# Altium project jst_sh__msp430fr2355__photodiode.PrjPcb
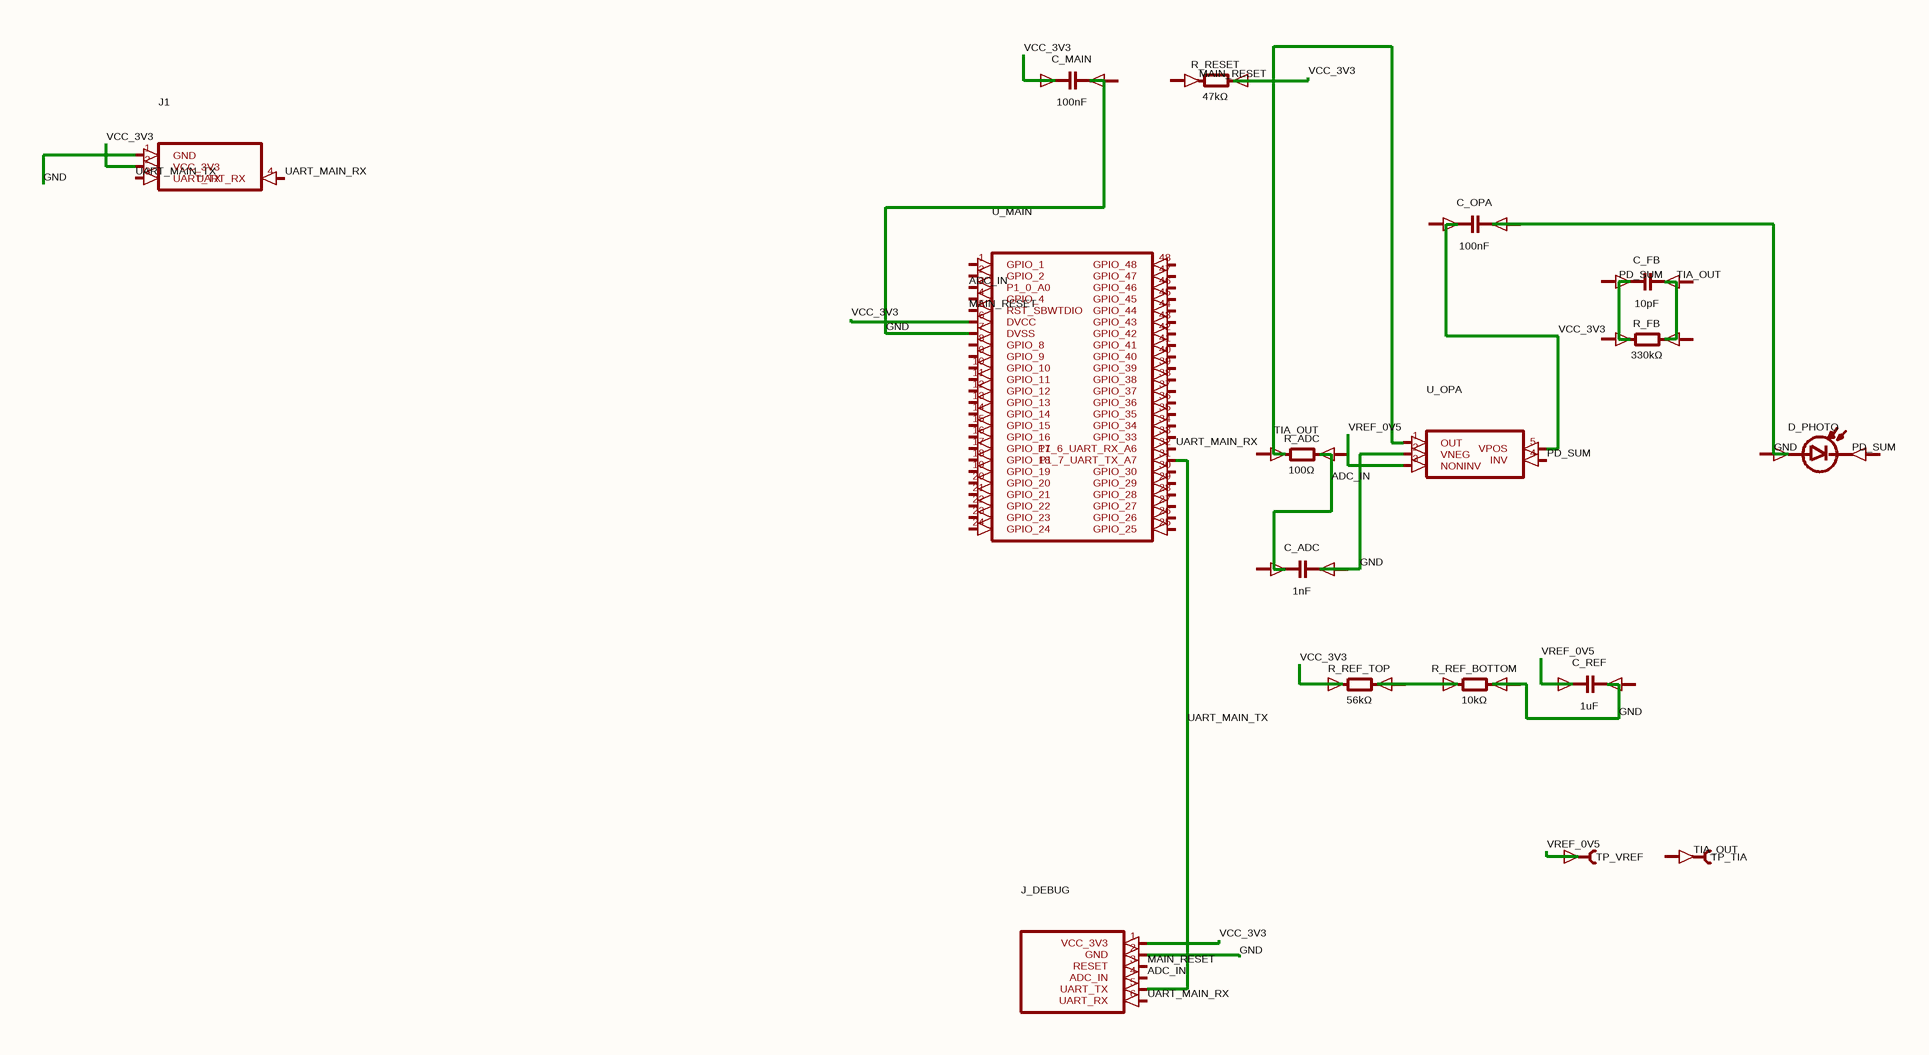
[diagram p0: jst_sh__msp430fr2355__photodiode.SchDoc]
1 sheet, 17 parts. Net scope: global (net labels, ports and power ports of the same name join across sheets).
Board file: jst_sh__msp430fr2355__photodiode.PcbDoc

## Sheet jst_sh__msp430fr2355__photodiode.SchDoc
size 212 x 135 mm

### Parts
C_ADC  1nF
C_FB  10pF
C_MAIN  100nF
C_OPA  100nF
C_REF  1uF
D_PHOTO  (no value)
J1  (no value)
J_DEBUG  (no value)
R_ADC  100Ω
R_FB  330kΩ
R_REF_BOTTOM  10kΩ
R_REF_TOP  56kΩ
R_RESET  47kΩ
TP_TIA  (no value)
TP_VREF  (no value)
U_MAIN  (no value)
U_OPA  (no value)

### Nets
ADC_IN: J_DEBUG.4(ADC_IN) U_MAIN.3(P1_0_A0)
GND: C_ADC.2(neg) C_MAIN.1(pos) C_OPA.2(neg) C_REF.1(pos) J1.1(GND) J1.2(VCC_3V3) J_DEBUG.1(VCC_3V3) J_DEBUG.2(GND) R_ADC.2(cathode) R_REF_BOTTOM.2(cathode) R_REF_TOP.1(anode) R_RESET.2(cathode) TP_VREF.1(pin1) U_MAIN.6(DVCC) U_MAIN.7(DVSS) U_OPA.2(VNEG) U_OPA.3(NONINV) U_OPA.5(VPOS)  [also labelled VCC_3V3, VREF_0V5]
MAIN_RESET: J_DEBUG.3(RESET) U_MAIN.5(RST_SBWTDIO)
PD_SUM: U_OPA.4(INV)
TIA_OUT: U_OPA.1(OUT)
UART_MAIN_RX: J1.4(UART_RX) J_DEBUG.6(UART_RX) U_MAIN.32(P1_6_UART_RX_A6)
UART_MAIN_TX: J1.3(UART_TX) J_DEBUG.5(UART_TX) U_MAIN.31(P1_7_UART_TX_A7)
NetR_REF_BOTTOM_1: R_REF_BOTTOM.1(anode) R_REF_TOP.2(cathode)

Not connected (* = marked no-connect by the designer): C_ADC 1(pos); C_FB 1(pos) 2(neg); C_MAIN 2(neg); C_OPA 1(pos); C_REF 2(neg); D_PHOTO 1(anode) 2(cathode); R_ADC 1(anode); R_FB 1(anode) 2(cathode); R_RESET 1(anode); TP_TIA 1(pin1); U_MAIN 1(GPIO_1) 2(GPIO_2) 4(GPIO_4) 8(GPIO_8) 9(GPIO_9) 10(GPIO_10) 11(GPIO_11) 12(GPIO_12) 13(GPIO_13) 14(GPIO_14) 15(GPIO_15) 16(GPIO_16) 17(GPIO_17) 18(GPIO_18) 19(GPIO_19) 20(GPIO_20) 21(GPIO_21) 22(GPIO_22) 23(GPIO_23) 24(GPIO_24) 25(GPIO_25) 26(GPIO_26) 27(GPIO_27) 28(GPIO_28) 29(GPIO_29) 30(GPIO_30) 33(GPIO_33) 34(GPIO_34) 35(GPIO_35) 36(GPIO_36) 37(GPIO_37) 38(GPIO_38) 39(GPIO_39) 40(GPIO_40) 41(GPIO_41) 42(GPIO_42) 43(GPIO_43) 44(GPIO_44) 45(GPIO_45) 46(GPIO_46) 47(GPIO_47) 48(GPIO_48)

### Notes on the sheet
- Labels drawn without touching a wire or pin: MAIN_RESET, PD_SUM, TIA_OUT

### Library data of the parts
C_ADC C_FB C_MAIN C_OPA C_REF = capacitor_right
D_PHOTO = photodiode_horz
J1 = J1
J_DEBUG = J_DEBUG
R_ADC R_FB R_REF_BOTTOM R_REF_TOP R_RESET = boxresistor_right
TP_TIA TP_VREF = testpoint_right
U_MAIN = U_MAIN
U_OPA = U_OPA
